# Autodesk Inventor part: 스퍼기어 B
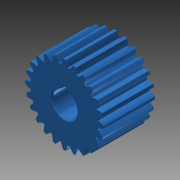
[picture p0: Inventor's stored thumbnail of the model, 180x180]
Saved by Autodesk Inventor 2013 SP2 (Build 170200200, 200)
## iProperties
Created: 2020-04
Part Number: 스퍼기어 B
Material: 강철, 연강
Document SubType Name: Modeling
Designer: mduedu
Categories: <?xml version="1.0" encoding="UTF-16"?> <MemberInstance><Categories><FamilyTemplate><FamilyTemplateParameter ValueType="xs:double" Id="1" ObjectReferenceKey="da
Density: 7.86 g/cm^3
Mass: 175.416 g
Surface Area: 76.8935 cm^2
Volume: 22.3176 cm^3
CustomPartVersion: 1
Author: mduedu
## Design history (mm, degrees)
sketch "Sketch1"
  geometry: C1 r 19.2 at (0, 0)
  constraints: 1 centre point
  dimensions: "d0" = 38.4 diameter of C1 (= da_da)
extrude "Extrusion1" new body sketch "Sketch1" distance "d1" = 25 (= da_b); taper "d2" = 0 deg
workplane "Work Plane2"
sketch "Sketch2"
  geometry: C1 r 19.2 at (0, 0) reference; C2 r 18 at (0, 0)
  constraints: 1 centre point, 1 coincident
  dimensions: "d3" = 36 diameter of C2 (= da_dw)
feature "피치 지름" sketch "Sketch2" dims "d4" = 10, "d5" = 0
workplane "Work Plane8"
workplane "Work Plane9"
feature "스퍼 기어" dims "da_b" = 25, "da_d" = 36, "da_aw" = 45, "da_da" = 38.4, "da_df" = 33.129, "da_dw" = 36, angle "da_beta" = 0 deg, "da_lefttooth" = 0, "da_righttooth" = 0
sketch "스케치3"
  geometry: L1 (-2, 5.657)-(2, 5.657); L2 (2, 5.657)-(2, 7.8); L3 (2, 7.8)-(-2, 7.8); L4 (-2, 7.8)-(-2, 5.657); A1 r 6 centre (0, 0) between (-2, 5.657) and (2, 5.657); 1 further point
  constraints: 8 end point, 2 parallel, 2 point on circle, 1 centre point, 1 coincident, 1 horizontal, 1 perpendicular
  dimensions: "d49" = 12 diameter of A1; "d51" = 4 distance of L2.end L3.end; "d52" = 13.8 dimension on A1 L3
extrude "돌출2" cut sketch "스케치3" stored distance "d53" = 10; taper "d54" = 0 deg
chamfer "모따기1" distance "d55" = 0.5; stored, may be unused: second distance "d56" = 2, angle "d57" = 45 deg
body "Solid1"
body "Srf1"
other parameters: "d16" = 45 (= da_aw), "d17" = 0, "d34" = 7.5 deg (computed from da_z), "d39" = 0, "d41" = 0, "d43" = 45 (= da_aw), "d46" = 45 (= da_aw), "d47" = 0, "d48" = 0
